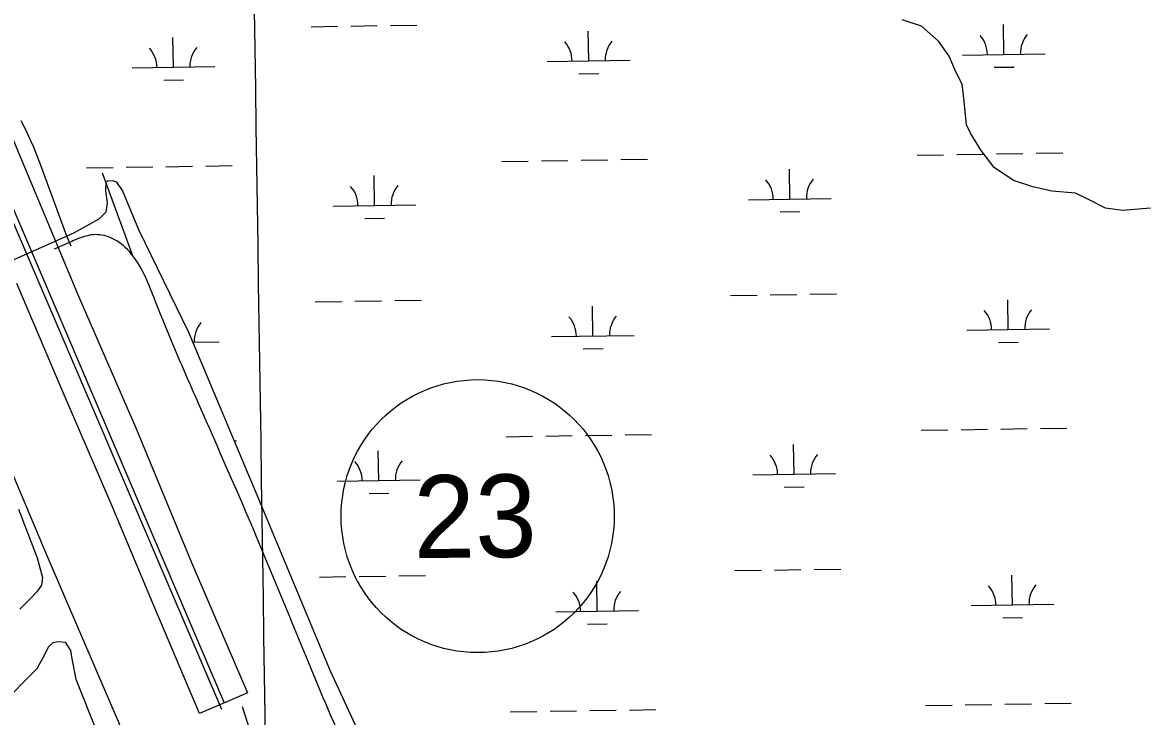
# Model space of a CAD drawing. Extents: x 3823584 to 3861785, y 301729 to 327625.
# Drawn here: x 3832593 to 3833950, y 323662 to 324501 of the extents above; entities that cross this region are included whole.
import ezdxf

# ---------------------------------------------------------------- set-up
doc = ezdxf.new("R2010")
doc.units = 0
for name, color, linetype in [('V-BRDG-OTLN', 7, 'Continuous'), ('V-GRID-MAJR', 7, 'Continuous'), ('V-ROAD-CNTR', 7, 'Continuous'), ('V-ROAD-IDEN', 7, 'Continuous'), ('V-SITE-VEGE', 7, 'Continuous'), ('V-WETL-SWMP', 7, 'Continuous')]:
    doc.layers.add(name, color=color, linetype=linetype)

msp = doc.modelspace()

# ---------------------------------------------------------------- linework, layer by layer
at = {"layer": 'V-BRDG-OTLN'}
for p, q in [((3832581.67, 324359.027), (3832659.2630000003, 324173.1999999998)), ((3832639.7660000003, 324059.544), (3832585.932, 324185.326)), ((3832659.2630000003, 324173.1999999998), (3832729.847, 324011.121)), ((3832700.061, 323919.047), (3832639.7660000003, 324059.544)), ((3832729.847, 324011.121), (3832797.159, 323848.367)), ((3832750.063, 323799.93599999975), (3832700.061, 323919.047)), ((3832797.159, 323848.367), (3832864.696, 323690.8669999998)), ((3832806.828, 323665.806), (3832750.063, 323799.93599999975)), ((3832864.696, 323690.8669999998), (3832851.812, 323685.289)), ((3832851.812, 323685.289), (3832820.736, 323671.829)), ((3832820.736, 323671.829), (3832806.828, 323665.80599999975))]:
    msp.add_line(p, q, dxfattribs=at)
msp.add_lwpolyline([(3832098.8176043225, 325406.0970195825), (3832371.691, 324767.382), (3832836.714, 323678.749)], dxfattribs=at)
at = {"layer": 'V-GRID-MAJR'}
msp.add_spline([(3833134.7290000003, 307237.467), (3833043.082, 313295.662), (3832951.406, 319355.783), (3832859.73, 325415.89900000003), (3832859.701, 325417.829)], degree=3, dxfattribs=at)
at = {"layer": 'V-ROAD-CNTR'}
for points in [[(3832833.7792929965, 323670.46063366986), (3832088.365783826, 325411.3991517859)], [(3832651.524, 324230.612), (3832646.539, 324242.775), (3832615.784, 324325.973), (3832606.044, 324350.934), (3832602.642, 324358.878), (3832599.0330000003, 324366.728), (3832595.22, 324374.482), (3832591.2060000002, 324382.13300000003)], [(3832726.37250781, 324218.96553665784), (3832689.5205815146, 324318.741337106)], [(3832647.77266501, 324234.19050620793), (3832631.1566982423, 324226.8585208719)], [(3832520.5829193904, 324097.38977981), (3832620.9887185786, 323859.4272557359), (3832701.2155581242, 323673.05562848)]]:
    msp.add_lwpolyline(points, dxfattribs=at)
msp.add_arc((3834224.225386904, 324117.54876224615), 1436.1526642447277, 197.9830178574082, 225.11311507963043, dxfattribs=at)
for points in [[(3833227.99150457, 323245.6094833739), (3833154.9586506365, 323333.3043079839), (3833076.507807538, 323449.9810746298), (3832994.2289720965, 323600.0917744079), (3832939.584081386, 323724.9065247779), (3832875.7852089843, 323879.16621625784), (3832805.951348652, 324039.6698952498), (3832753.324453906, 324164.447645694), (3832726.37250781, 324218.96553665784), (3832707.055546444, 324236.9155007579), (3832686.0945883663, 324244.39448579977), (3832666.5016275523, 324241.9834906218), (3832647.77266501, 324234.19050620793)], [(3832701.2155581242, 323673.05562848), (3832758.9344426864, 323540.40489378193), (3832844.4572716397, 323369.1662362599), (3832919.476121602, 323247.9464786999), (3832998.4269637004, 323140.5656934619), (3833096.3367678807, 323026.1319223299)]]:
    msp.add_spline(points, degree=3, dxfattribs=at)
at = {"layer": 'V-ROAD-IDEN'}
msp.add_circle((3833142.935697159, 323904.2924400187), 165.00000000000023, dxfattribs=at)
msp.add_circle((3833142.935697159, 323904.2924400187), 165.00000000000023, dxfattribs=at)
at = {"layer": 'V-SITE-VEGE'}
for points in [[(3833790.4, 324310.175), (3833767.1180000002, 324325.702), (3833751.599, 324346.408), (3833738.663, 324367.113), (3833733.49, 324377.466), (3833730.904, 324405.935), (3833728.3170000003, 324426.63800000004), (3833720.555, 324442.17), (3833712.795, 324460.28500000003), (3833699.86, 324478.39900000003), (3833679.169, 324496.518), (3833655.8850000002, 324504.284)], [(3833955.9560000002, 324276.53), (3833922.328, 324273.941), (3833901.633, 324276.53), (3833880.938, 324286.881), (3833865.418, 324294.64900000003), (3833836.963, 324297.233), (3833813.682, 324302.411), (3833790.4, 324310.175)]]:
    msp.add_lwpolyline(points, dxfattribs=at)
at = {"layer": 'V-WETL-SWMP'}
for p, q in [((3832941.5610282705, 324495.95379779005), (3832973.557212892, 324496.44713807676)), ((3832989.5553052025, 324496.6938082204), (3833021.551489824, 324497.18714850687)), ((3833037.549582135, 324497.4338186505), (3833069.545766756, 324497.9271589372)), ((3833277.0809701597, 324454.69161866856), (3833276.525916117, 324490.6873000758)), ((3833778.929127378, 324462.42947606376), (3833778.374073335, 324498.4251574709)), ((3832775.2328129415, 324446.9537612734), (3832774.6777588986, 324482.9494426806)), ((3833728.9350889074, 324461.6586318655), (3833828.923165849, 324463.2003202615)), ((3832725.2387744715, 324446.1829170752), (3832825.226851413, 324447.7246054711)), ((3833227.086931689, 324453.9207744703), (3833327.0750086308, 324455.46246286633)), ((3833767.1684758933, 324446.815324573), (3833791.165614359, 324447.1853297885)), ((3833265.320318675, 324439.0774671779), (3833289.317457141, 324439.4474723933)), ((3832763.472161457, 324431.3396097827), (3832787.469299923, 324431.70961499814)), ((3833673.949141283, 324340.72567834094), (3833705.945325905, 324341.21901862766)), ((3833721.9434182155, 324341.46568877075), (3833753.9396028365, 324341.95902905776)), ((3833769.9376951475, 324342.2056992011), (3833801.933879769, 324342.69903948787)), ((3833817.93197208, 324342.9457096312), (3833849.9281567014, 324343.439049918)), ((3832670.252826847, 324325.2499635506), (3832702.2490114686, 324325.7433038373)), ((3832718.247103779, 324325.9899739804), (3832750.2432884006, 324326.4833142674)), ((3832766.2413807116, 324326.72998441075), (3832798.2375653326, 324327.2233246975)), ((3832814.2356576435, 324327.46999484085), (3832846.231842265, 324327.96333512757)), ((3833172.1009840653, 324332.98782094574), (3833204.0971686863, 324333.48116123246)), ((3833220.095260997, 324333.7278313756), (3833252.091445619, 324334.22117166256)), ((3833268.0895379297, 324334.46784180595), (3833300.0857225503, 324334.96118209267)), ((3833316.0838148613, 324335.20785223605), (3833348.079999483, 324335.70119252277)), ((3833018.3097648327, 324279.8685810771), (3833017.75471079, 324315.8642624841)), ((3833520.1579220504, 324287.6064384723), (3833519.602868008, 324323.6021198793)), ((3833470.1638835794, 324286.8355942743), (3833570.151960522, 324288.3772826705)), ((3832968.3157263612, 324279.09773687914), (3833068.3038033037, 324280.6394252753)), ((3833508.397270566, 324271.9922869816), (3833532.394409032, 324272.362292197)), ((3833006.549113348, 324264.2544295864), (3833030.546251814, 324264.6244348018)), ((3832946.6902672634, 324163.31870578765), (3832978.6864518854, 324163.8120460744)), ((3832994.684544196, 324164.058716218), (3833026.680728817, 324164.5520565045)), ((3833042.678821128, 324164.7987266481), (3833074.6750057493, 324165.2920669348)), ((3833448.5384244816, 324171.05656318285), (3833480.534609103, 324171.54990346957)), ((3833496.5327014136, 324171.7965736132), (3833528.528886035, 324172.2899138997)), ((3833544.526978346, 324172.5365840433), (3833576.523162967, 324173.02992433)), ((3833784.0583663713, 324129.79438406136), (3833783.5033123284, 324165.7900654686)), ((3833282.210209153, 324122.05652666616), (3833281.65515511, 324158.0522080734)), ((3833232.216170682, 324121.2856824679), (3833332.204247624, 324122.82737086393)), ((3833734.0643279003, 324129.0235398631), (3833834.0524048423, 324130.5652282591)), ((3832798.6748556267, 324114.6010293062), (3832830.356090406, 324115.08951346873)), ((3833772.2977148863, 324114.1802325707), (3833796.294853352, 324114.5502377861)), ((3833270.4495576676, 324106.4423751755), (3833294.446696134, 324106.8123803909)), ((3833177.2302230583, 324000.35272894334), (3833209.2264076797, 324000.84606923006)), ((3833225.2244999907, 324001.0927393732), (3833257.2206846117, 324001.58607966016)), ((3833273.218776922, 324001.83274980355), (3833305.214961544, 324002.32609009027)), ((3833321.213053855, 324002.57276023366), (3833353.2092384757, 324003.0661005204)), ((3833679.078380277, 324008.09058633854), (3833711.0745648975, 324008.58392662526)), ((3833727.0726572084, 324008.8305967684), (3833759.0688418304, 324009.32393705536)), ((3833775.066934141, 324009.5706071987), (3833807.063118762, 324010.06394748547)), ((3833823.061211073, 324010.3106176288), (3833855.0573956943, 324010.8039579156)), ((3832848.8069819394, 323995.2888621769), (3832851.361081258, 323995.32824312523)), ((3833525.287161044, 323954.9713464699), (3833524.7321070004, 323990.9670278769)), ((3833023.4390038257, 323947.2334890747), (3833022.8839497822, 323983.2291704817)), ((3832973.444965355, 323946.46264487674), (3833073.433042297, 323948.0043332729)), ((3833475.293122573, 323954.2005022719), (3833575.281199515, 323955.7421906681)), ((3833011.6783523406, 323931.619337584), (3833035.675490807, 323931.9893427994)), ((3833513.526509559, 323939.3571949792), (3833537.5236480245, 323939.7272001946)), ((3833453.6676634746, 323838.4214711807), (3833485.6638480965, 323838.9148114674)), ((3833501.661940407, 323839.161481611), (3833533.658125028, 323839.6548218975)), ((3833549.656217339, 323839.9014920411), (3833581.6524019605, 323840.39483232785)), ((3832951.819506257, 323830.6836137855), (3832983.8156908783, 323831.17695407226)), ((3832999.813783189, 323831.4236242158), (3833031.8099678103, 323831.91696450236)), ((3833047.8080601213, 323832.1636346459), (3833079.8042447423, 323832.6569749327)), ((3833287.339448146, 323789.421434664), (3833286.784394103, 323825.4171160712)), ((3833789.1876053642, 323797.1592920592), (3833788.6325513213, 323833.1549734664)), ((3833739.1935668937, 323796.38844786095), (3833839.1816438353, 323797.93013625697)), ((3833237.3454096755, 323788.6505904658), (3833337.333486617, 323790.19227886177)), ((3833777.4269538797, 323781.5451405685), (3833801.4240923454, 323781.9151457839)), ((3833275.5787966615, 323773.8072831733), (3833299.575935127, 323774.1772883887)), ((3833684.2076192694, 323675.4554943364), (3833716.2038038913, 323675.9488346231)), ((3833732.201896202, 323676.19550476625), (3833764.198080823, 323676.6888450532)), ((3833780.196173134, 323676.9355151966), (3833812.1923577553, 323677.4288554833)), ((3833828.1904500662, 323677.6755256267), (3833860.1866346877, 323678.1688659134)), ((3833182.3594620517, 323667.7176369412), (3833214.3556466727, 323668.21097722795)), ((3833230.353738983, 323668.45764737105), (3833262.349923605, 323668.95098765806)), ((3833278.348015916, 323669.1976578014), (3833310.3442005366, 323669.6909980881)), ((3833326.3422928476, 323669.9376682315), (3833358.3384774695, 323670.4310085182))]:
    msp.add_line(p, q, dxfattribs=at)
for points in [[(3832997.424, 323647.086), (3832965.0100000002, 323716.851), (3832880.386, 323920.142), (3832793.801, 324126.212), (3832733.63, 324250.297), (3832713.74, 324297.851), (3832706.683, 324308.17), (3832701.948, 324309.778), (3832695.619, 324309.02400000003), (3832693.633, 324307.454), (3832693.181, 324297.57300000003), (3832695.074, 324282.935), (3832693.429, 324271.875), (3832685.078, 324263.22500000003), (3832655.333, 324246.792), (3832641.143, 324240.31), (3832561.875, 324205.184)], [(3832587.875, 323912.882), (3832610.467, 323853.848), (3832617.052, 323830.09), (3832615.8140000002, 323821.005), (3832610.2320000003, 323812.734), (3832602.278, 323804.478), (3832589.555, 323791.9)], [(3832579.9760000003, 323689.26300000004), (3832596.676, 323706.167), (3832610.594, 323720.319), (3832619.382, 323736.083), (3832624.185, 323746.33400000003), (3832629.7490000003, 323751.441), (3832636.0810000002, 323752.591), (3832644.38, 323752.148), (3832651.042, 323741.831), (3832652.566, 323731.939), (3832657.17, 323707.402), (3832682.502, 323643.608), (3832719.9620000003, 323557.605), (3832756.2430000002, 323472.795), (3832787.136, 323413.713), (3832815.3030000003, 323361.76300000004), (3832857.972, 323287.98600000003), (3832908.921, 323210.20900000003), (3832956.366, 323141.939), (3832996.381, 323087.944), (3833053.332, 323022.783), (3833106.37, 322964.76), (3833167.667, 322899.179)]]:
    msp.add_lwpolyline(points, dxfattribs=at)
for centre, radius, start, end in [((3833221.837300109, 324454.31469095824), 35.24628790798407, 0.11153821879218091, 41.65519655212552), ((3833332.30999902, 324456.0180388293), 35.246287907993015, 140.11153411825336, 181.6551924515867), ((3833723.685457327, 324462.05254835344), 35.24628790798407, 0.11153821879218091, 41.65519655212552), ((3833834.1581562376, 324463.7558962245), 35.246287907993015, 140.11153411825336, 181.6551924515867), ((3832719.989142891, 324446.5768335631), 35.24628790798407, 0.11153821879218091, 41.65519655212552), ((3832830.4618418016, 324448.2801814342), 35.246287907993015, 140.11153411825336, 181.6551924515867), ((3833464.914252, 324287.229510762), 35.24628790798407, 0.11153821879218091, 41.65519655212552), ((3833575.3869509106, 324288.93285863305), 35.246287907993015, 140.11153411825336, 181.6551924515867), ((3832963.0660947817, 324279.49165336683), 35.24628790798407, 0.11153821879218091, 41.65519655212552), ((3833073.538793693, 324281.19500123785), 35.246287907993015, 140.11153411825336, 181.6551924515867), ((3833728.814696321, 324129.41745635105), 35.24628790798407, 0.11153821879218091, 41.65519655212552), ((3833839.287395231, 324131.1208042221), 35.246287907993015, 140.11153411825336, 181.6551924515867), ((3832835.5910807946, 324115.6450894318), 35.246287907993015, 140.11153411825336, 181.6551924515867), ((3833226.966539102, 324121.6795989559), 35.24628790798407, 0.11153821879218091, 41.65519655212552), ((3833337.4392380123, 324123.3829468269), 35.246287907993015, 140.11153411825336, 181.6551924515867), ((3833470.043490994, 323954.5944187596), 35.24628790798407, 0.11153821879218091, 41.65519655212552), ((3833580.5161899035, 323956.29776663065), 35.246287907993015, 140.11153411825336, 181.6551924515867), ((3832968.1953337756, 323946.85656136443), 35.24628790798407, 0.11153821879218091, 41.65519655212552), ((3833078.6680326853, 323948.5599092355), 35.246287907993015, 140.11153411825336, 181.6551924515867), ((3833232.0957780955, 323789.04450695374), 35.24628790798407, 0.11153821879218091, 41.65519655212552), ((3833342.568477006, 323790.74785482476), 35.246287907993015, 140.11153411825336, 181.6551924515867), ((3833733.9439353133, 323796.7823643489), 35.24628790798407, 0.11153821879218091, 41.65519655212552), ((3833844.416634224, 323798.48571221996), 35.246287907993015, 140.11153411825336, 181.6551924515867)]:
    msp.add_arc(centre, radius, start, end, dxfattribs=at)

# ---------------------------------------------------------------- texts
at = {"layer": 'V-ROAD-IDEN'}
msp.add_text('23', height=100.00000199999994, rotation=0.6162221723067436, dxfattribs=at).set_placement((3833065.9189277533, 323853.4611926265))

doc.saveas('drawing.dxf')
